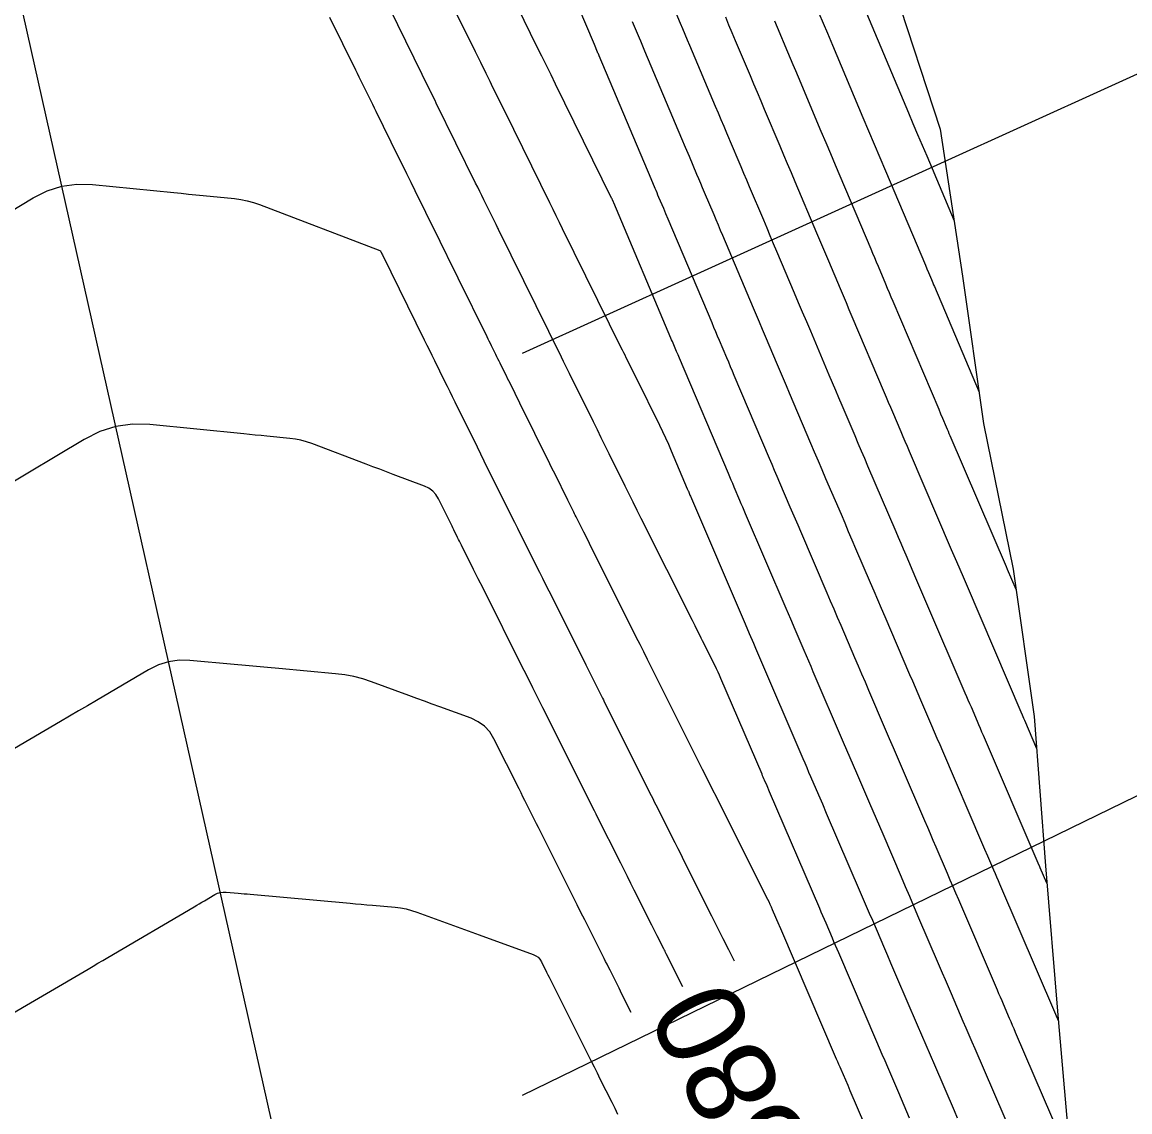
# Model space of a CAD drawing. Extents: x 954385 to 988206, y 1868364 to 1924553.
# Drawn here: x 957973.4 to 958048.1, y 1919067.8 to 1919141.2 of the extents above; entities that cross this region are included whole.
import ezdxf

# ---------------------------------------------------------------- set-up
doc = ezdxf.new("R2010")
doc.units = 0
for name, color, linetype in [('24', 7, 'Continuous'), ('26', 7, 'Continuous'), ('5', 7, 'Continuous'), ('6', 7, 'Continuous'), ('7', 7, 'Continuous'), ('Default', 7, 'Continuous')]:
    doc.layers.add(name, color=color, linetype=linetype)

msp = doc.modelspace()

# ---------------------------------------------------------------- linework, layer by layer
at = {"layer": '24'}
msp.add_lwpolyline([(958002.021, 1919239.295), (958004.432, 1919229.588), (958007.744, 1919220.082), (958011.352, 1919210.643), (958015.035, 1919201.221), (958017.626, 1919191.554), (958020.15, 1919181.871), (958023.018, 1919172.266), (958025.931, 1919162.671), (958029.184, 1919153.153), (958032.173, 1919143.575), (958035.293, 1919134.026), (958036.808, 1919124.117), (958038.226, 1919114.187), (958040.213, 1919104.384), (958041.632, 1919094.454), (958042.392, 1919084.376), (958043.229, 1919074.315), (958044.113, 1919064.265)], dxfattribs=at)
at = {"layer": '26'}
for points in [[(958007.131, 1919118.928), (958086.103, 1919154.821), (958082.614, 1919149.94), (958086.103, 1919154.821), (958080.131, 1919155.402)], [(958007.131, 1919068.928), (958070.501, 1919099.785), (958067.143, 1919094.813), (958070.501, 1919099.785), (958064.516, 1919100.208)]]:
    msp.add_lwpolyline(points, dxfattribs=at)
at = {"layer": '6'}
for points in [[(958040.232, 1919066.046), (958037.649, 1919072.044), (958037.449, 1919072.509), (958037.249, 1919072.973), (958037.05, 1919073.438), (958036.851, 1919073.902), (958036.054, 1919075.761), (958035.855, 1919076.226), (958035.655, 1919076.69), (958035.456, 1919077.155), (958035.257, 1919077.62), (958033.801, 1919081.017), (958033.521, 1919081.669), (958033.241, 1919082.322), (958032.961, 1919082.975), (958032.681, 1919083.628), (958031.442, 1919086.512), (958031.22, 1919087.027), (958030.999, 1919087.543), (958030.777, 1919088.059), (958030.556, 1919088.575), (958029.669, 1919090.638), (958029.448, 1919091.154), (958029.226, 1919091.67), (958029.005, 1919092.186), (958028.784, 1919092.702), (958026.741, 1919097.468), (958026.589, 1919097.823), (958026.436, 1919098.178), (958026.284, 1919098.533), (958026.132, 1919098.889), (958025.523, 1919100.309), (958025.219, 1919101.019), (958024.914, 1919101.73), (958022.181, 1919108.107), (958022.084, 1919108.333), (958021.987, 1919108.559), (958021.89, 1919108.785), (958021.793, 1919109.011), (958021.405, 1919109.916), (958021.308, 1919110.142), (958021.212, 1919110.369), (958021.115, 1919110.595), (958021.019, 1919110.821), (958017.721, 1919118.598), (958017.625, 1919118.824), (958017.529, 1919119.049), (958017.338, 1919119.501), (958017.29, 1919119.614), (958017.242, 1919119.727), (958017.194, 1919119.84), (958017.146, 1919119.953), (958013.29, 1919129.064), (958013.271, 1919129.11), (958013.2, 1919129.278), (958013.188, 1919129.307), (958013.175, 1919129.335), (958013.162, 1919129.363), (958013.148, 1919129.391), (958009.374, 1919137.067), (958009.066, 1919137.693), (958008.757, 1919138.32), (958008.449, 1919138.946), (958008.14, 1919139.572), (958006.808, 1919142.274)], [(958040.409, 1919103.014), (958039.837, 1919104.349), (958039.76, 1919104.528), (958035.973, 1919113.358), (958035.91, 1919113.505), (958035.847, 1919113.653), (958035.784, 1919113.801), (958035.721, 1919113.949), (958035.47, 1919114.54), (958035.345, 1919114.835), (958035.219, 1919115.131), (958032.128, 1919122.423), (958032.003, 1919122.717), (958031.879, 1919123.011), (958031.754, 1919123.305), (958031.63, 1919123.599), (958031.132, 1919124.775), (958031.007, 1919125.069), (958030.883, 1919125.363), (958030.758, 1919125.657), (958030.634, 1919125.952), (958028.552, 1919130.87), (958028.234, 1919131.62), (958027.917, 1919132.371), (958027.6, 1919133.121), (958027.283, 1919133.872), (958025.736, 1919137.537), (958025.559, 1919137.957), (958025.382, 1919138.376), (958025.205, 1919138.796), (958025.028, 1919139.215), (958024.32, 1919140.894), (958024.142, 1919141.313)], [(958017.94, 1919076.239), (958017.145, 1919077.828), (958017.026, 1919078.066), (958016.827, 1919078.462), (958016.787, 1919078.542), (958016.748, 1919078.621), (958016.708, 1919078.7), (958016.668, 1919078.78), (958016.22, 1919079.673), (958016.132, 1919079.848), (958016.044, 1919080.023), (958015.956, 1919080.199), (958015.867, 1919080.374), (958014.674, 1919082.748), (958014.446, 1919083.202), (958014.218, 1919083.657), (958013.99, 1919084.111), (958013.762, 1919084.565), (958012.139, 1919087.802), (958012.11, 1919087.862), (958012, 1919088.081), (958009.193, 1919093.685), (958009.025, 1919094.021), (958008.856, 1919094.357), (958008.688, 1919094.693), (958008.52, 1919095.029), (958007.846, 1919096.373), (958007.678, 1919096.709), (958007.51, 1919097.045), (958007.342, 1919097.381), (958007.173, 1919097.717), (958004.478, 1919103.1), (958004.161, 1919103.732), (958003.845, 1919104.364), (958003.024, 1919106.004), (958002.96, 1919106.131), (958002.896, 1919106.259), (958002.833, 1919106.387), (958002.769, 1919106.514), (958002.516, 1919107.026), (958002.453, 1919107.154), (958002.39, 1919107.282), (958002.326, 1919107.409), (958002.263, 1919107.537), (958001.48, 1919109.12), (958001.308, 1919109.403), (958001.093, 1919109.64), (958000.836, 1919109.83), (958000.538, 1919109.974), (957998.433, 1919110.769), (957997.976, 1919110.942), (957997.518, 1919111.115), (957997.061, 1919111.287), (957996.604, 1919111.46), (957992.945, 1919112.843), (957992.579, 1919112.967), (957992.207, 1919113.067), (957991.829, 1919113.142), (957991.446, 1919113.192), (957989.9, 1919113.343), (957989.514, 1919113.38), (957989.128, 1919113.418), (957988.742, 1919113.456), (957988.355, 1919113.494), (957982.014, 1919114.121), (957980.849, 1919114.147), (957979.725, 1919113.99), (957978.641, 1919113.651), (957977.599, 1919113.13), (957971.945, 1919109.741)]]:
    msp.add_lwpolyline(points, dxfattribs=at)
at = {"layer": '7'}
for points in [[(958044.088, 1919064.546), (958040.38, 1919073.156), (958040.278, 1919073.393), (958040.176, 1919073.63), (958040.074, 1919073.867), (958039.973, 1919074.104), (958039.566, 1919075.053), (958039.464, 1919075.29), (958039.363, 1919075.528), (958039.261, 1919075.765), (958039.159, 1919076.002), (958036.549, 1919082.091), (958036.359, 1919082.535), (958036.169, 1919082.979), (958035.978, 1919083.423), (958035.787, 1919083.867), (958035.025, 1919085.642), (958034.834, 1919086.086), (958034.644, 1919086.53), (958034.453, 1919086.974), (958034.262, 1919087.418), (958032.687, 1919091.084), (958032.42, 1919091.706), (958032.154, 1919092.327), (958031.887, 1919092.949), (958031.621, 1919093.57), (958030.491, 1919096.205), (958030.256, 1919096.752), (958030.022, 1919097.299), (958029.787, 1919097.847), (958029.553, 1919098.394), (958028.615, 1919100.582), (958028.381, 1919101.129), (958028.146, 1919101.676), (958027.912, 1919102.223), (958027.677, 1919102.77), (958025.897, 1919106.924), (958025.721, 1919107.334), (958025.545, 1919107.744), (958025.37, 1919108.154), (958025.194, 1919108.564), (958024.49, 1919110.205), (958024.314, 1919110.615), (958024.139, 1919111.026), (958023.964, 1919111.436), (958023.79, 1919111.847), (958021.419, 1919117.437), (958021.294, 1919117.731), (958021.169, 1919118.026), (958021.044, 1919118.321), (958020.919, 1919118.615), (958020.419, 1919119.794), (958020.294, 1919120.089), (958020.169, 1919120.384), (958020.044, 1919120.678), (958019.92, 1919120.973), (958016.959, 1919127.969), (958016.809, 1919128.324), (958016.659, 1919128.679), (958016.337, 1919129.439), (958016.272, 1919129.591), (958016.208, 1919129.743), (958016.144, 1919129.895), (958016.08, 1919130.047), (958015.695, 1919130.96), (958015.566, 1919131.264), (958012.311, 1919138.977), (958012.284, 1919139.041), (958012.257, 1919139.105), (958012.23, 1919139.169), (958012.203, 1919139.233), (958011.985, 1919139.747), (958009.789, 1919144.936)], [(958001.91, 1919143.414), (958003.951, 1919139.278), (958004.132, 1919138.911), (958004.312, 1919138.544), (958004.674, 1919137.811), (958004.764, 1919137.628), (958004.855, 1919137.444), (958004.945, 1919137.261), (958005.035, 1919137.078), (958005.863, 1919135.394), (958006.031, 1919135.053), (958006.199, 1919134.711), (958006.367, 1919134.369), (958006.535, 1919134.028), (958008.965, 1919129.086), (958009.179, 1919128.65), (958009.394, 1919128.214), (958009.608, 1919127.778), (958009.823, 1919127.343), (958013.779, 1919119.322), (958013.862, 1919119.155), (958013.945, 1919118.987), (958014.028, 1919118.819), (958014.111, 1919118.652), (958014.525, 1919117.814), (958014.691, 1919117.479), (958014.774, 1919117.311), (958016.365, 1919114.094), (958016.574, 1919113.664), (958016.777, 1919113.23), (958016.973, 1919112.794), (958017.163, 1919112.355), (958018.248, 1919109.796), (958018.266, 1919109.754), (958018.284, 1919109.711), (958018.302, 1919109.669), (958018.32, 1919109.627), (958018.429, 1919109.374), (958018.465, 1919109.29), (958022.151, 1919100.689), (958022.431, 1919100.036), (958022.711, 1919099.383), (958022.851, 1919099.057), (958022.991, 1919098.731), (958026.036, 1919091.628), (958026.167, 1919091.32), (958026.299, 1919091.013), (958026.431, 1919090.706), (958026.563, 1919090.399), (958027.09, 1919089.171), (958027.354, 1919088.557), (958027.618, 1919087.942), (958029.905, 1919082.618), (958030.11, 1919082.142), (958030.314, 1919081.665), (958030.519, 1919081.189), (958030.723, 1919080.712), (958031.54, 1919078.806), (958031.744, 1919078.33), (958031.948, 1919077.853), (958032.153, 1919077.377), (958032.357, 1919076.9), (958033.741, 1919073.671), (958034.032, 1919072.994), (958034.322, 1919072.316), (958034.614, 1919071.639), (958034.905, 1919070.962), (958036.232, 1919067.882), (958036.443, 1919067.391)], [(958042.489, 1919083.205), (958042.046, 1919084.241), (958042.012, 1919084.32), (958041.91, 1919084.556), (958038.212, 1919093.166), (958038.11, 1919093.403), (958038.008, 1919093.641), (958037.906, 1919093.878), (958037.804, 1919094.116), (958037.397, 1919095.067), (958037.295, 1919095.304), (958037.193, 1919095.542), (958037.091, 1919095.78), (958036.989, 1919096.017), (958034.336, 1919102.209), (958034.001, 1919102.99), (958033.666, 1919103.771), (958032.997, 1919105.333), (958032.83, 1919105.723), (958032.662, 1919106.114), (958032.495, 1919106.504), (958032.327, 1919106.895), (958030.43, 1919111.318), (958030.212, 1919111.829), (958029.993, 1919112.34), (958029.776, 1919112.851), (958029.558, 1919113.362), (958028.691, 1919115.408), (958028.474, 1919115.919), (958028.257, 1919116.431), (958028.04, 1919116.942), (958027.823, 1919117.454), (958026.569, 1919120.411), (958026.297, 1919121.054), (958026.024, 1919121.697), (958025.752, 1919122.341), (958025.479, 1919122.984), (958024.292, 1919125.79), (958024.069, 1919126.317), (958023.846, 1919126.844), (958023.623, 1919127.37), (958023.4, 1919127.897), (958022.444, 1919130.155), (958022.253, 1919130.606), (958022.063, 1919131.057), (958021.872, 1919131.508), (958021.681, 1919131.96), (958020.919, 1919133.765), (958020.729, 1919134.217), (958020.538, 1919134.668), (958020.348, 1919135.119), (958020.157, 1919135.571), (958018.427, 1919139.67), (958018.269, 1919140.045), (958018.111, 1919140.419), (958017.953, 1919140.793), (958017.794, 1919141.167), (958017.161, 1919142.663)], [(958033.237, 1919067.382), (958033.053, 1919067.809), (958032.869, 1919068.237), (958032.684, 1919068.665), (958032.5, 1919069.093), (958031.763, 1919070.804), (958031.579, 1919071.231), (958031.395, 1919071.659), (958031.211, 1919072.087), (958031.028, 1919072.515), (958028.455, 1919078.518), (958028.348, 1919078.767), (958028.241, 1919079.016), (958028.135, 1919079.265), (958028.028, 1919079.514), (958027.601, 1919080.51), (958027.494, 1919080.759), (958027.387, 1919081.008), (958027.28, 1919081.257), (958027.173, 1919081.506), (958023.794, 1919089.373), (958023.625, 1919089.766), (958023.456, 1919090.16), (958023.414, 1919090.258), (958023.372, 1919090.356), (958023.33, 1919090.455), (958023.287, 1919090.553), (958020.519, 1919097.011), (958020.424, 1919097.228), (958020.326, 1919097.444), (958020.224, 1919097.659), (958020.119, 1919097.872), (958019.284, 1919099.541), (958019.185, 1919099.739), (958018.779, 1919100.55), (958018.59, 1919100.925), (958015.148, 1919107.802), (958014.877, 1919108.344), (958014.606, 1919108.887), (958014.336, 1919109.43), (958014.067, 1919109.973), (958012.992, 1919112.147), (958012.723, 1919112.69), (958012.454, 1919113.234), (958012.186, 1919113.777), (958011.917, 1919114.32), (958010.314, 1919117.561), (958010.178, 1919117.836), (958010.042, 1919118.111), (958009.906, 1919118.386), (958009.771, 1919118.661), (958005.521, 1919127.277), (958005.49, 1919127.338), (958005.46, 1919127.399), (958005.355, 1919127.614), (958005.34, 1919127.645), (958004.537, 1919129.277), (958004.398, 1919129.559), (958004.259, 1919129.841), (958004.12, 1919130.123), (958003.982, 1919130.406), (958001.331, 1919135.794), (958001.245, 1919135.968), (958001.057, 1919136.351), (958001.021, 1919136.424), (958000.95, 1919136.568), (958000.926, 1919136.617), (957998.188, 1919142.175)], [(958027.12, 1919141.85), (958027.69, 1919140.5), (958027.918, 1919139.96), (958028.032, 1919139.69), (958030.084, 1919134.828), (958030.464, 1919133.928), (958030.844, 1919133.028), (958031.225, 1919132.128), (958031.606, 1919131.228), (958034.3, 1919124.862), (958034.401, 1919124.623), (958034.502, 1919124.384), (958034.705, 1919123.907), (958034.755, 1919123.787), (958034.806, 1919123.668), (958034.856, 1919123.548), (958034.907, 1919123.429), (958037.922, 1919116.319)], [(958030.327, 1919141.844), (958033.156, 1919135.141), (958033.464, 1919134.413), (958033.771, 1919133.685), (958034.079, 1919132.957), (958034.387, 1919132.229), (958036.235, 1919127.863)], [(958032.197, 1919062.345), (958029.237, 1919069.217), (958029.083, 1919069.574), (958028.929, 1919069.931), (958028.622, 1919070.645), (958028.545, 1919070.824), (958028.468, 1919071.002), (958028.391, 1919071.181), (958028.315, 1919071.36), (958024.553, 1919080.135), (958024.469, 1919080.33), (958024.442, 1919080.395), (958024.002, 1919081.419), (958023.924, 1919081.596), (958023.844, 1919081.772), (958023.761, 1919081.947), (958023.675, 1919082.121), (958020.577, 1919088.292), (958020.253, 1919088.938), (958019.929, 1919089.584), (958019.605, 1919090.23), (958019.281, 1919090.876), (958015.821, 1919097.786), (958015.568, 1919098.291), (958015.315, 1919098.797), (958015.062, 1919099.302), (958014.809, 1919099.807), (958011.659, 1919106.098), (958011.468, 1919106.481), (958011.276, 1919106.863), (958010.803, 1919107.808), (958010.752, 1919107.91), (958010.702, 1919108.011), (958010.652, 1919108.112), (958010.602, 1919108.213), (958010.351, 1919108.719), (958010.201, 1919109.023), (958009.313, 1919110.819), (958009.148, 1919111.152), (958008.983, 1919111.485), (958008.818, 1919111.818), (958008.654, 1919112.151), (958007.976, 1919113.522), (958007.808, 1919113.861), (958007.641, 1919114.2), (958007.473, 1919114.54), (958007.305, 1919114.879), (958006.301, 1919116.905), (958006.219, 1919117.07), (958006.138, 1919117.235), (958006.056, 1919117.4), (958005.975, 1919117.564), (958005.634, 1919118.256), (958005.56, 1919118.404), (958005.487, 1919118.553), (958005.414, 1919118.701), (958005.341, 1919118.85), (958005.049, 1919119.443), (958004.975, 1919119.592), (958004.902, 1919119.74), (958004.829, 1919119.889), (958004.756, 1919120.037), (958002.804, 1919124), (958002.682, 1919124.246), (958002.561, 1919124.493), (958002.439, 1919124.739), (958002.318, 1919124.985), (958001.832, 1919125.97), (958001.711, 1919126.216), (958001.589, 1919126.463), (958001.468, 1919126.709), (958001.347, 1919126.955), (957999.908, 1919129.879), (957999.628, 1919130.448), (957999.348, 1919131.017), (957999.068, 1919131.587), (957998.788, 1919132.156), (957997.276, 1919135.229), (957997.162, 1919135.461), (957997.048, 1919135.693), (957996.934, 1919135.924), (957996.82, 1919136.156), (957996.363, 1919137.083), (957996.249, 1919137.315), (957996.135, 1919137.546), (957996.021, 1919137.778), (957995.906, 1919138.01), (957994.153, 1919141.563)], [(958014.535, 1919141.296), (958014.999, 1919140.2), (958015.091, 1919139.981), (958015.184, 1919139.762), (958015.276, 1919139.543), (958015.369, 1919139.324), (958017.862, 1919133.417), (958018.116, 1919132.814), (958018.371, 1919132.21), (958018.88, 1919131.004), (958019.008, 1919130.702), (958019.135, 1919130.4), (958019.263, 1919130.099), (958019.39, 1919129.797), (958020.029, 1919128.288), (958020.178, 1919127.936), (958020.327, 1919127.584), (958020.476, 1919127.232), (958020.625, 1919126.88), (958022.693, 1919121.994), (958022.895, 1919121.517), (958023.097, 1919121.041), (958023.299, 1919120.564), (958023.501, 1919120.087), (958024.309, 1919118.181), (958024.511, 1919117.705), (958024.713, 1919117.228), (958024.915, 1919116.752), (958025.117, 1919116.275), (958026.56, 1919112.873), (958026.813, 1919112.277), (958027.066, 1919111.683), (958027.32, 1919111.088), (958027.575, 1919110.494), (958028.611, 1919108.078), (958028.858, 1919107.503), (958029.104, 1919106.929), (958029.35, 1919106.354), (958029.596, 1919105.78), (958030.581, 1919103.482), (958030.827, 1919102.908), (958031.074, 1919102.333), (958031.32, 1919101.759), (958031.566, 1919101.184), (958033.239, 1919097.28), (958033.423, 1919096.85), (958033.607, 1919096.421), (958033.792, 1919095.991), (958033.976, 1919095.562), (958034.712, 1919093.843), (958034.897, 1919093.414), (958035.081, 1919092.984), (958035.265, 1919092.554), (958035.45, 1919092.125), (958038.086, 1919085.987), (958038.288, 1919085.517), (958038.49, 1919085.047), (958038.894, 1919084.106), (958038.995, 1919083.871), (958039.096, 1919083.636), (958039.197, 1919083.401), (958039.298, 1919083.166), (958043.065, 1919074.375), (958043.107, 1919074.277), (958043.264, 1919073.912)], [(958020.814, 1919141.605), (958021.038, 1919141.076), (958021.262, 1919140.547), (958021.485, 1919140.017), (958022.48, 1919137.66), (958022.72, 1919137.091), (958022.96, 1919136.522), (958023.2, 1919135.953), (958023.441, 1919135.384), (958024.482, 1919132.916), (958024.736, 1919132.315), (958024.99, 1919131.714), (958025.244, 1919131.113), (958025.498, 1919130.512), (958026.968, 1919127.041), (958027.166, 1919126.572), (958027.364, 1919126.104), (958027.563, 1919125.635), (958027.761, 1919125.166), (958028.554, 1919123.291), (958028.753, 1919122.823), (958028.951, 1919122.354), (958029.15, 1919121.886), (958029.348, 1919121.417), (958031.521, 1919116.292), (958031.661, 1919115.963), (958031.801, 1919115.633), (958031.941, 1919115.303), (958032.08, 1919114.974), (958032.64, 1919113.655), (958032.78, 1919113.326), (958032.92, 1919112.996), (958033.061, 1919112.667), (958033.202, 1919112.338), (958036.043, 1919105.711), (958036.132, 1919105.505), (958036.221, 1919105.299), (958036.309, 1919105.092), (958036.398, 1919104.886), (958036.84, 1919103.853), (958037.105, 1919103.234), (958040.739, 1919094.755), (958040.818, 1919094.572), (958040.916, 1919094.343), (958040.955, 1919094.252), (958040.975, 1919094.206), (958041.795, 1919092.297)], [(957969.456, 1919126.585), (957974.16, 1919129.415), (957975.105, 1919129.889), (957976.087, 1919130.197), (957977.107, 1919130.338), (957978.164, 1919130.314), (957983.626, 1919129.765), (957984.123, 1919129.715), (957984.62, 1919129.665), (957985.117, 1919129.616), (957985.614, 1919129.566), (957987.724, 1919129.354), (957988.156, 1919129.296), (957988.581, 1919129.21), (957989, 1919129.096), (957989.412, 1919128.954), (957997.52, 1919125.85), (957997.541, 1919125.839), (957997.559, 1919125.826), (957997.574, 1919125.809), (957997.586, 1919125.789), (957997.659, 1919125.641), (957997.694, 1919125.569), (958000.522, 1919119.834), (958000.694, 1919119.487), (958000.865, 1919119.139), (958001.036, 1919118.792), (958001.208, 1919118.444), (958001.893, 1919117.054), (958002.064, 1919116.706), (958002.235, 1919116.359), (958002.407, 1919116.012), (958002.579, 1919115.664), (958003.62, 1919113.558), (958003.851, 1919113.091), (958004.082, 1919112.624), (958004.313, 1919112.158), (958004.544, 1919111.691), (958006.383, 1919107.979), (958006.592, 1919107.557), (958006.802, 1919107.136), (958007.012, 1919106.714), (958007.222, 1919106.293), (958008.066, 1919104.609), (958008.276, 1919104.188), (958008.487, 1919103.767), (958008.698, 1919103.346), (958008.909, 1919102.925), (958011.264, 1919098.217), (958011.412, 1919097.921), (958011.561, 1919097.624), (958012.396, 1919095.955), (958012.461, 1919095.825), (958012.526, 1919095.695), (958012.591, 1919095.565), (958012.656, 1919095.435), (958015.818, 1919089.121), (958015.922, 1919088.915), (958016.025, 1919088.708), (958016.129, 1919088.501), (958016.233, 1919088.294), (958017.213, 1919086.343), (958017.41, 1919085.949), (958017.608, 1919085.555), (958017.806, 1919085.16), (958018.004, 1919084.766), (958019.89, 1919081.011), (958020.27, 1919080.254), (958020.65, 1919079.496), (958021.03, 1919078.739), (958021.409, 1919077.981), (958021.409, 1919077.981)], [(958014.469, 1919074.496), (958013.847, 1919075.739), (958013.646, 1919076.14), (958013.445, 1919076.541), (958013.044, 1919077.344), (958012.943, 1919077.544), (958012.843, 1919077.745), (958012.742, 1919077.945), (958012.641, 1919078.146), (958011.336, 1919080.747), (958011.084, 1919081.247), (958010.833, 1919081.748), (958010.582, 1919082.248), (958010.331, 1919082.748), (958008.482, 1919086.434), (958008.351, 1919086.695), (958008.22, 1919086.956), (958008.089, 1919087.217), (958007.958, 1919087.478), (958007.435, 1919088.523), (958007.304, 1919088.784), (958007.174, 1919089.045), (958007.043, 1919089.306), (958006.912, 1919089.567), (958005.219, 1919092.947), (958004.935, 1919093.407), (958004.583, 1919093.791), (958004.162, 1919094.098), (958003.673, 1919094.328), (958001.579, 1919095.096), (958001.056, 1919095.288), (958000.532, 1919095.48), (958000.009, 1919095.672), (957999.485, 1919095.864), (957996.973, 1919096.785), (957996.375, 1919096.982), (957995.768, 1919097.14), (957995.153, 1919097.257), (957994.528, 1919097.335), (957990.705, 1919097.683), (957989.957, 1919097.751), (957989.21, 1919097.819), (957988.463, 1919097.887), (957987.715, 1919097.955), (957984.726, 1919098.227), (957983.991, 1919098.239), (957983.281, 1919098.139), (957982.597, 1919097.926), (957981.938, 1919097.602), (957978.427, 1919095.534), (957977.821, 1919095.177), (957977.215, 1919094.82), (957976.609, 1919094.463), (957976.004, 1919094.106), (957972.905, 1919092.281)], [(957971.976, 1919073.97), (957977.863, 1919077.426), (957978.191, 1919077.619), (957978.52, 1919077.812), (957978.848, 1919078.005), (957979.177, 1919078.198), (957985.003, 1919081.619), (957985.178, 1919081.722), (957985.354, 1919081.825), (957985.529, 1919081.928), (957985.704, 1919082.031), (957986.406, 1919082.444), (957986.585, 1919082.533), (957986.77, 1919082.59), (957986.963, 1919082.617), (957987.162, 1919082.614), (957987.973, 1919082.54), (957988.176, 1919082.522), (957988.378, 1919082.504), (957988.581, 1919082.485), (957988.784, 1919082.467), (957995.513, 1919081.864), (957995.893, 1919081.83), (957996.272, 1919081.796), (957996.652, 1919081.762), (957997.031, 1919081.728), (957998.549, 1919081.592), (957998.926, 1919081.546), (957999.298, 1919081.476), (957999.664, 1919081.381), (958000.025, 1919081.263), (958002.253, 1919080.451), (958002.743, 1919080.272), (958003.234, 1919080.094), (958003.725, 1919079.915), (958004.215, 1919079.736), (958007.869, 1919078.406), (958008.041, 1919078.325), (958008.189, 1919078.217), (958008.314, 1919078.083), (958008.414, 1919077.921), (958008.766, 1919077.22), (958008.854, 1919077.044), (958008.942, 1919076.869), (958009.029, 1919076.694), (958009.117, 1919076.518), (958011.567, 1919071.624), (958011.766, 1919071.227), (958011.964, 1919070.831), (958012.163, 1919070.434), (958012.362, 1919070.037), (958013.156, 1919068.449), (958013.355, 1919068.052), (958013.554, 1919067.656)]]:
    msp.add_lwpolyline(points, dxfattribs=at)
at = {"layer": 'Default'}
msp.add_line((958200.602, 1918129.717), (957843.865, 1919719.405), dxfattribs=at)

# ---------------------------------------------------------------- texts
at = {"layer": '5'}
msp.add_text('580', height=6, rotation=116.66088, dxfattribs=at).set_placement((958026.871, 1919065.138))

doc.saveas('drawing.dxf')
